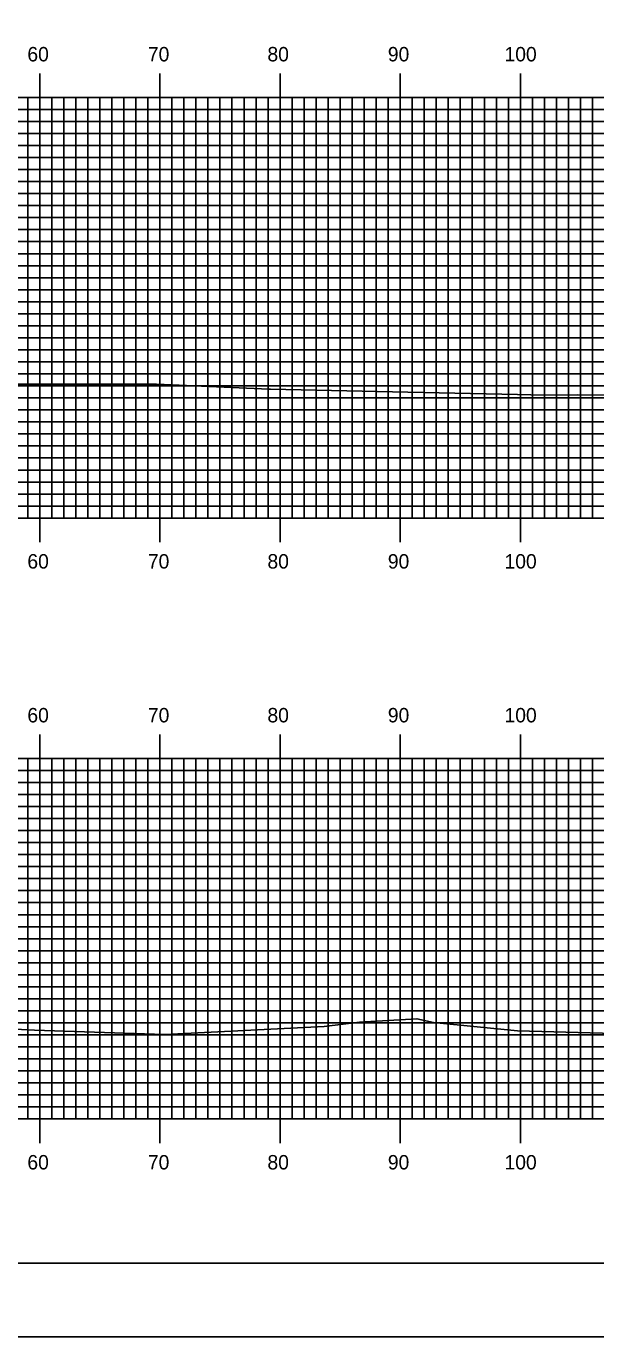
# Model space of a CAD drawing. Extents: x 1761397 to 1761741, y 442591 to 442811.
# Drawn here: x 1761622.1 to 1761669.5, y 442590.5 to 442699.6 of the extents above; entities that cross this region are included whole.
import ezdxf

# ---------------------------------------------------------------- set-up
doc = ezdxf.new("R2010")
doc.units = 0
for name, color, linetype in [('BORDER', 7, 'Continuous'), ('H_V ANNOTATION', 7, 'Continuous'), ('MAJOR', 7, 'Continuous'), ('MINOR', 7, 'Continuous'), ('PLOT BOUNDARY', 7, 'Continuous'), ('S_Roadway_Centerline', 7, 'Continuous')]:
    doc.layers.add(name, color=color, linetype=linetype)

msp = doc.modelspace()

# ---------------------------------------------------------------- linework, layer by layer
at = {"layer": 'BORDER'}
msp.add_lwpolyline([(1761413.64, 442596.67), (1761733.64, 442596.67), (1761733.64, 442806.67), (1761413.64, 442806.67)], close=True, dxfattribs=at)
at = {"layer": 'MAJOR'}
for p, q in [((1761623.24, 442695.67), (1761623.24, 442693.67)), ((1761633.24, 442695.67), (1761633.24, 442693.67)), ((1761643.24, 442695.67), (1761643.24, 442693.67)), ((1761653.24, 442695.67), (1761653.24, 442693.67)), ((1761663.24, 442695.67), (1761663.24, 442693.67)), ((1761423.24, 442693.67), (1761703.24, 442693.67)), ((1761423.24, 442693.67), (1761703.24, 442693.67)), ((1761623.24, 442658.67), (1761623.24, 442693.67)), ((1761633.24, 442658.67), (1761633.24, 442693.67)), ((1761643.24, 442658.67), (1761643.24, 442693.67)), ((1761653.24, 442658.67), (1761653.24, 442693.67)), ((1761663.24, 442658.67), (1761663.24, 442693.67)), ((1761423.24, 442688.67), (1761703.24, 442688.67)), ((1761423.24, 442683.67), (1761703.24, 442683.67)), ((1761423.24, 442678.67), (1761703.24, 442678.67)), ((1761423.24, 442673.67), (1761703.24, 442673.67)), ((1761423.24, 442668.67), (1761703.24, 442668.67)), ((1761423.24, 442663.67), (1761703.24, 442663.67)), ((1761423.24, 442658.67), (1761703.24, 442658.67)), ((1761423.24, 442658.67), (1761703.24, 442658.67)), ((1761623.24, 442656.66), (1761623.24, 442658.67)), ((1761633.24, 442656.66), (1761633.24, 442658.67)), ((1761643.24, 442656.66), (1761643.24, 442658.67)), ((1761653.24, 442656.66), (1761653.24, 442658.67)), ((1761663.24, 442656.66), (1761663.24, 442658.67)), ((1761623.24, 442640.67), (1761623.24, 442638.67)), ((1761633.24, 442640.67), (1761633.24, 442638.67)), ((1761643.24, 442640.67), (1761643.24, 442638.67)), ((1761653.24, 442640.67), (1761653.24, 442638.67)), ((1761663.24, 442640.67), (1761663.24, 442638.67)), ((1761423.24, 442638.67), (1761703.24, 442638.67)), ((1761423.24, 442638.67), (1761703.24, 442638.67)), ((1761623.24, 442608.67), (1761623.24, 442638.67)), ((1761633.24, 442608.67), (1761633.24, 442638.67)), ((1761643.24, 442608.67), (1761643.24, 442638.67)), ((1761653.24, 442608.67), (1761653.24, 442638.67)), ((1761663.24, 442608.67), (1761663.24, 442638.67)), ((1761423.24, 442633.67), (1761703.24, 442633.67)), ((1761423.24, 442628.67), (1761703.24, 442628.67)), ((1761423.24, 442623.67), (1761703.24, 442623.67)), ((1761423.24, 442618.67), (1761703.24, 442618.67)), ((1761423.24, 442613.67), (1761703.24, 442613.67)), ((1761423.24, 442608.67), (1761703.24, 442608.67)), ((1761423.24, 442608.67), (1761703.24, 442608.67)), ((1761623.24, 442606.66), (1761623.24, 442608.67)), ((1761633.24, 442606.66), (1761633.24, 442608.67)), ((1761643.24, 442606.66), (1761643.24, 442608.67)), ((1761653.24, 442606.66), (1761653.24, 442608.67)), ((1761663.24, 442606.66), (1761663.24, 442608.67))]:
    msp.add_line(p, q, dxfattribs=at)
at = {"layer": 'MINOR'}
for p, q in [((1761622.24, 442658.67), (1761622.24, 442693.67)), ((1761624.24, 442658.67), (1761624.24, 442693.67)), ((1761625.24, 442658.67), (1761625.24, 442693.67)), ((1761626.24, 442658.67), (1761626.24, 442693.67)), ((1761627.24, 442658.67), (1761627.24, 442693.67)), ((1761628.24, 442658.67), (1761628.24, 442693.67)), ((1761629.24, 442658.67), (1761629.24, 442693.67)), ((1761630.24, 442658.67), (1761630.24, 442693.67)), ((1761631.24, 442658.67), (1761631.24, 442693.67)), ((1761632.24, 442658.67), (1761632.24, 442693.67)), ((1761634.24, 442658.67), (1761634.24, 442693.67)), ((1761635.24, 442658.67), (1761635.24, 442693.67)), ((1761636.24, 442658.67), (1761636.24, 442693.67)), ((1761637.24, 442658.67), (1761637.24, 442693.67)), ((1761638.24, 442658.67), (1761638.24, 442693.67)), ((1761639.24, 442658.67), (1761639.24, 442693.67)), ((1761640.24, 442658.67), (1761640.24, 442693.67)), ((1761641.24, 442658.67), (1761641.24, 442693.67)), ((1761642.24, 442658.67), (1761642.24, 442693.67)), ((1761644.24, 442658.67), (1761644.24, 442693.67)), ((1761645.24, 442658.67), (1761645.24, 442693.67)), ((1761646.24, 442658.67), (1761646.24, 442693.67)), ((1761647.24, 442658.67), (1761647.24, 442693.67)), ((1761648.24, 442658.67), (1761648.24, 442693.67)), ((1761649.24, 442658.67), (1761649.24, 442693.67)), ((1761650.24, 442658.67), (1761650.24, 442693.67)), ((1761651.24, 442658.67), (1761651.24, 442693.67)), ((1761652.24, 442658.67), (1761652.24, 442693.67)), ((1761654.24, 442658.67), (1761654.24, 442693.67)), ((1761655.24, 442658.67), (1761655.24, 442693.67)), ((1761656.24, 442658.67), (1761656.24, 442693.67)), ((1761657.24, 442658.67), (1761657.24, 442693.67)), ((1761658.24, 442658.67), (1761658.24, 442693.67)), ((1761659.24, 442658.67), (1761659.24, 442693.67)), ((1761660.24, 442658.67), (1761660.24, 442693.67)), ((1761661.24, 442658.67), (1761661.24, 442693.67)), ((1761662.24, 442658.67), (1761662.24, 442693.67)), ((1761664.24, 442658.67), (1761664.24, 442693.67)), ((1761665.24, 442658.67), (1761665.24, 442693.67)), ((1761666.24, 442658.67), (1761666.24, 442693.67)), ((1761667.24, 442658.67), (1761667.24, 442693.67)), ((1761668.24, 442658.67), (1761668.24, 442693.67)), ((1761669.24, 442658.67), (1761669.24, 442693.67)), ((1761423.24, 442692.67), (1761703.24, 442692.67)), ((1761423.24, 442691.67), (1761703.24, 442691.67)), ((1761423.24, 442690.67), (1761703.24, 442690.67)), ((1761423.24, 442689.67), (1761703.24, 442689.67)), ((1761423.24, 442687.67), (1761703.24, 442687.67)), ((1761423.24, 442686.67), (1761703.24, 442686.67)), ((1761423.24, 442685.67), (1761703.24, 442685.67)), ((1761423.24, 442684.67), (1761703.24, 442684.67)), ((1761423.24, 442682.67), (1761703.24, 442682.67)), ((1761423.24, 442681.67), (1761703.24, 442681.67)), ((1761423.24, 442680.67), (1761703.24, 442680.67)), ((1761423.24, 442679.67), (1761703.24, 442679.67)), ((1761423.24, 442677.67), (1761703.24, 442677.67)), ((1761423.24, 442676.67), (1761703.24, 442676.67)), ((1761423.24, 442675.67), (1761703.24, 442675.67)), ((1761423.24, 442674.67), (1761703.24, 442674.67)), ((1761423.24, 442672.67), (1761703.24, 442672.67)), ((1761423.24, 442671.67), (1761703.24, 442671.67)), ((1761423.24, 442670.67), (1761703.24, 442670.67)), ((1761423.24, 442669.67), (1761703.24, 442669.67)), ((1761423.24, 442667.67), (1761703.24, 442667.67)), ((1761423.24, 442666.67), (1761703.24, 442666.67)), ((1761423.24, 442665.67), (1761703.24, 442665.67)), ((1761423.24, 442664.67), (1761703.24, 442664.67)), ((1761423.24, 442662.67), (1761703.24, 442662.67)), ((1761423.24, 442661.67), (1761703.24, 442661.67)), ((1761423.24, 442660.67), (1761703.24, 442660.67)), ((1761423.24, 442659.67), (1761703.24, 442659.67)), ((1761622.24, 442608.67), (1761622.24, 442638.67)), ((1761624.24, 442608.67), (1761624.24, 442638.67)), ((1761625.24, 442608.67), (1761625.24, 442638.67)), ((1761626.24, 442608.67), (1761626.24, 442638.67)), ((1761627.24, 442608.67), (1761627.24, 442638.67)), ((1761628.24, 442608.67), (1761628.24, 442638.67)), ((1761629.24, 442608.67), (1761629.24, 442638.67)), ((1761630.24, 442608.67), (1761630.24, 442638.67)), ((1761631.24, 442608.67), (1761631.24, 442638.67)), ((1761632.24, 442608.67), (1761632.24, 442638.67)), ((1761634.24, 442608.67), (1761634.24, 442638.67)), ((1761635.24, 442608.67), (1761635.24, 442638.67)), ((1761636.24, 442608.67), (1761636.24, 442638.67)), ((1761637.24, 442608.67), (1761637.24, 442638.67)), ((1761638.24, 442608.67), (1761638.24, 442638.67)), ((1761639.24, 442608.67), (1761639.24, 442638.67)), ((1761640.24, 442608.67), (1761640.24, 442638.67)), ((1761641.24, 442608.67), (1761641.24, 442638.67)), ((1761642.24, 442608.67), (1761642.24, 442638.67)), ((1761644.24, 442608.67), (1761644.24, 442638.67)), ((1761645.24, 442608.67), (1761645.24, 442638.67)), ((1761646.24, 442608.67), (1761646.24, 442638.67)), ((1761647.24, 442608.67), (1761647.24, 442638.67)), ((1761648.24, 442608.67), (1761648.24, 442638.67)), ((1761649.24, 442608.67), (1761649.24, 442638.67)), ((1761650.24, 442608.67), (1761650.24, 442638.67)), ((1761651.24, 442608.67), (1761651.24, 442638.67)), ((1761652.24, 442608.67), (1761652.24, 442638.67)), ((1761654.24, 442608.67), (1761654.24, 442638.67)), ((1761655.24, 442608.67), (1761655.24, 442638.67)), ((1761656.24, 442608.67), (1761656.24, 442638.67)), ((1761657.24, 442608.67), (1761657.24, 442638.67)), ((1761658.24, 442608.67), (1761658.24, 442638.67)), ((1761659.24, 442608.67), (1761659.24, 442638.67)), ((1761660.24, 442608.67), (1761660.24, 442638.67)), ((1761661.24, 442608.67), (1761661.24, 442638.67)), ((1761662.24, 442608.67), (1761662.24, 442638.67)), ((1761664.24, 442608.67), (1761664.24, 442638.67)), ((1761665.24, 442608.67), (1761665.24, 442638.67)), ((1761666.24, 442608.67), (1761666.24, 442638.67)), ((1761667.24, 442608.67), (1761667.24, 442638.67)), ((1761668.24, 442608.67), (1761668.24, 442638.67)), ((1761669.24, 442608.67), (1761669.24, 442638.67)), ((1761423.24, 442637.67), (1761703.24, 442637.67)), ((1761423.24, 442636.67), (1761703.24, 442636.67)), ((1761423.24, 442635.67), (1761703.24, 442635.67)), ((1761423.24, 442634.67), (1761703.24, 442634.67)), ((1761423.24, 442632.67), (1761703.24, 442632.67)), ((1761423.24, 442631.67), (1761703.24, 442631.67)), ((1761423.24, 442630.67), (1761703.24, 442630.67)), ((1761423.24, 442629.67), (1761703.24, 442629.67)), ((1761423.24, 442627.67), (1761703.24, 442627.67)), ((1761423.24, 442626.67), (1761703.24, 442626.67)), ((1761423.24, 442625.67), (1761703.24, 442625.67)), ((1761423.24, 442624.67), (1761703.24, 442624.67)), ((1761423.24, 442622.67), (1761703.24, 442622.67)), ((1761423.24, 442621.67), (1761703.24, 442621.67)), ((1761423.24, 442620.67), (1761703.24, 442620.67)), ((1761423.24, 442619.67), (1761703.24, 442619.67)), ((1761423.24, 442617.67), (1761703.24, 442617.67)), ((1761423.24, 442616.67), (1761703.24, 442616.67)), ((1761423.24, 442615.67), (1761703.24, 442615.67)), ((1761423.24, 442614.67), (1761703.24, 442614.67)), ((1761423.24, 442612.67), (1761703.24, 442612.67)), ((1761423.24, 442611.67), (1761703.24, 442611.67)), ((1761423.24, 442610.67), (1761703.24, 442610.67)), ((1761423.24, 442609.67), (1761703.24, 442609.67))]:
    msp.add_line(p, q, dxfattribs=at)
at = {"layer": 'PLOT BOUNDARY'}
msp.add_lwpolyline([(1761397.45, 442590.55), (1761737.45, 442590.55), (1761737.45, 442810.55), (1761397.45, 442810.55)], close=True, dxfattribs=at)
at = {"layer": 'S_Roadway_Centerline'}
for points in [[(1761621.05, 442669.82), (1761632.88, 442669.81), (1761632.96, 442669.81), (1761642.33, 442669.39), (1761642.44, 442669.39), (1761653.87, 442669.16), (1761663.01, 442668.95), (1761665.23, 442668.91), (1761668, 442668.92), (1761683.96, 442668.86), (1761687.42, 442668.92), (1761691.89, 442668.73), (1761700.2, 442668.64), (1761703.24, 442668.6)], [(1761617.39, 442616.34), (1761622.81, 442616.06), (1761633.63, 442615.69), (1761646.9, 442616.37), (1761649.84, 442616.72), (1761654.63, 442617.01), (1761656, 442616.69), (1761662.99, 442616), (1761674.1, 442615.71), (1761675.03, 442615.66), (1761675.67, 442615.66), (1761684.03, 442615.36), (1761684.21, 442615.36), (1761696.16, 442615.48), (1761703.24, 442615.18)]]:
    msp.add_lwpolyline(points, dxfattribs=at)

# ---------------------------------------------------------------- texts
at = {"layer": 'H_V ANNOTATION'}
for s, p in [('60', (1761622.21, 442696.67)), ('70', (1761632.24, 442696.67)), ('80', (1761642.19, 442696.67)), ('90', (1761652.21, 442696.67)), ('100', (1761661.92, 442696.67)), ('60', (1761622.21, 442654.47)), ('70', (1761632.24, 442654.47)), ('80', (1761642.19, 442654.47)), ('90', (1761652.21, 442654.47)), ('100', (1761661.92, 442654.47)), ('60', (1761622.21, 442641.67)), ('70', (1761632.24, 442641.67)), ('80', (1761642.19, 442641.67)), ('90', (1761652.21, 442641.67)), ('100', (1761661.92, 442641.67)), ('60', (1761622.21, 442604.47)), ('70', (1761632.24, 442604.47)), ('80', (1761642.19, 442604.47)), ('90', (1761652.21, 442604.47)), ('100', (1761661.92, 442604.47))]:
    msp.add_text(s, height=1.2, dxfattribs=at).set_placement(p)

doc.saveas('drawing.dxf')
